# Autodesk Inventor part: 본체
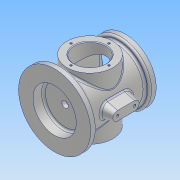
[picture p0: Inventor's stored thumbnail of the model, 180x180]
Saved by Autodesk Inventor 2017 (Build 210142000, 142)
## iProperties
Part Number: 본체
Material: 알루미늄 6061
Document SubType Name: Modeling
Designer: Administrator
Density: 2.7 g/cm^3
Appearance: 알루미늄 - 평지
Author: Administrator
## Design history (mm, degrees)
sketch "스케치4"
  geometry: C1 r 55 at (0, 0); 1 further point
  constraints: 1 centre point, 1 coincident
  dimensions: "d9" = 110 diameter of C1
extrude "돌출4" new body sketch "스케치4" distance "d10" = 10; taper "d11" = 0 deg
sketch "스케치5"
  geometry: C1 r 55 at (0, 0) reference; C2 r 40 at (0, 0)
  constraints: 1 centre point, 1 coincident
  dimensions: "d12" = 80 diameter of C2
extrude "돌출5" join sketch "스케치5" distance "d13" = 88; taper "d14" = 0 deg
sketch "스케치6"
  geometry: C1 r 40 at (0, 0) reference; C2 r 47 at (0, 0)
  constraints: 1 centre point, 1 coincident
  dimensions: "d15" = 94 diameter of C2
extrude "돌출6" join sketch "스케치6" distance "d16" = 10; taper "d17" = 0 deg
sketch "스케치7"
  geometry: L1 (54, 129.53)-(54, -154.754); L2 (0, 0)-(143.846, 0); L3 (89, 47)-(54, 47); L4 (54, -47)-(89, -47); L5 (89, -47)-(89, 47); 1 further point
  constraints: 10 end point, 3 point on line, 2 horizontal, 1 parallel, 1 vertical
  dimensions: "d18" = 108 diameter of L2.start L1; "d19" = 70 diameter of L5 L1; "d20" = 94 distance of L4.end L3.start
revolve "회전1" sketch "스케치7" stored, may be unused: angle "d21" = 360 deg
sketch "스케치8"
  geometry: C1 r 35 at (0, 0) reference; C2 r 24 at (0, 0); 1 further point
  constraints: 1 centre point, 1 coincident
  dimensions: "d22" = 48 diameter of C2
extrude "돌출7" cut sketch "스케치8" stored distance "d23" = 0; taper "d24" = 0 deg
sketch "스케치9"
  geometry: C1 r 47 at (0, 0) reference; C2 r 35 at (0, 0)
  constraints: 1 centre point, 1 coincident
  dimensions: "d25" = 70 diameter of C2
extrude "돌출8" cut sketch "스케치9" distance "d26" = 7; taper "d27" = 0 deg
sketch "스케치10"
  geometry: C1 r 35 at (0, 0) reference
sketch "스케치11"
  geometry: C1 r 35 at (0, 0) reference; C2 r 33 at (0, 0)
  constraints: 1 centre point, 1 coincident
  dimensions: "d28" = 66 diameter of C2
extrude "돌출9" cut sketch "스케치11" distance "d29" = 79; taper "d30" = 0 deg
sketch "스케치12"
  geometry: C1 r 33 at (0, 0) reference; C2 r 5 at (0, 0)
  constraints: 1 centre point, 1 coincident
  dimensions: "d31" = 10 diameter of C2
hole "구멍1" sketch "스케치12" at (0, 0) diameter "d32" = 10; stored, may be unused: countersink angle "d36" = 90 deg, drill point angle "d38" = 0 deg; dims "d33" = 6, "d34" = 4, "d35" = 2, "d37" = 8
sketch "스케치13"
  geometry: C1 r 5 at (0, 0) reference; C2 r 5 at (0, 0) reference; C3 r 33 at (0, 0)
  constraints: 1 centre point, 1 coincident
  dimensions: "d39" = 66 diameter of C3
extrude "돌출10" cut sketch "스케치13" distance "d40" = 16; taper "d41" = 0 deg
node "작업 평면1"
node "작업 평면2"
sketch "스케치22"
  geometry: L1 (67, 0)-(41, 0); L2 (67, 7)-(41, 7); L3 (41, -7)-(67, -7); L4 (0, 55)-(0, -55) reference; A1 r 7 centre (67, 0) between (67, -7) and (67, 7); A2 r 7 centre (41, 0) between (41, 7) and (41, -7); 2 further points
  constraints: 8 end point, 4 point on circle, 4 tangent, 2 centre point, 1 horizontal, 1 midpoint, 1 parallel
  dimensions: "d62" = 14 diameter of A2; "d63" = 40 dimension on A2 A1; "d64" = 54 distance from line of L4 point (54, 0)
extrude "돌출12" join sketch "스케치22" stored distance "d65" = 16; taper "d66" = 0 deg
feature "면 기울기2" dims angle "d67" = 15 deg
feature "면 기울기3" dims angle "d68" = 15 deg
feature "면 기울기4" dims angle "d69" = 15 deg
feature "면 기울기5" dims angle "d70" = 15 deg
sketch "스케치23"
  geometry: C1 r 24 at (0, 0) reference; 2 further points
  dimensions: "d71" = 29 distance of C1.centre point (0, 29)
hole "구멍2" sketch "스케치23" at (0, 29) diameter "d72" = 3.242; stored, may be unused: countersink angle "d76" = 90 deg, drill point angle "d78" = 118 deg; dims "d73" = 6, "d74" = 4, "d75" = 2, "d77" = 8
sketch "스케치24"
  geometry: C1 r 35 at (0, 0) reference; 1 further point
  dimensions: "d82" = 40 distance of point (40, 0) C1.centre
hole "구멍3" sketch "스케치24" at (40, 0) diameter "d83" = 3.242; stored, may be unused: countersink angle "d87" = 90 deg, drill point angle "d89" = 118 deg; dims "d84" = 6, "d85" = 4, "d86" = 2, "d88" = 8
sketch "스케치25"
  geometry: L1 (-7, 67)-(-7, 41) reference; L2 (7, 41)-(7, 67) reference; A1 r 7 centre (0, 41) between (-7, 41) and (7, 41) reference; A2 r 7 centre (0, 67) between (7, 67) and (-7, 67) reference; A3 r 7 centre (0, 41) between (-7, 41) and (7, 41) reference; A4 r 7 centre (0, 67) between (7, 67) and (-7, 67) reference; 1 further point
hole "구멍4" sketch "스케치25" at (0, 67), (0, 41) diameter "d93" = 4.134; stored, may be unused: countersink angle "d97" = 90 deg, drill point angle "d99" = 118 deg; dims "d94" = 6, "d95" = 4, "d96" = 2, "d98" = 8
sketch "스케치26"
  geometry: C1 r 55 at (0, 0) reference; C2 r 50 at (0, 0)
  constraints: 1 centre point, 1 coincident, 1 other
  dimensions: "d100" = 100 diameter of C2
feature "엠보싱1" sketch "스케치26" dims "d18" = 108, "d19" = 70, "d20" = 94, "d101" = 0.5, "d102" = 0
fillet "모깎기1" dims "d103" = 3
chamfer "모따기1" distance "d104" = 1; stored, may be unused: second distance "d105" = 2, angle "d106" = 45 deg
fillet "모깎기2" dims "d107" = 3
chamfer "모따기2" distance "d108" = 1; stored, may be unused: second distance "d109" = 2, angle "d110" = 45 deg
node "솔리드2"
pattern_circular "원형 패턴1" dims angle "d80" = 360 deg
mirror "미러1"
pattern_circular "원형 패턴2" dims angle "d91" = 360 deg
node "투영된 루프1"
node "투영된 루프4"
other parameters: "d42" = 55, "d58" = 54
